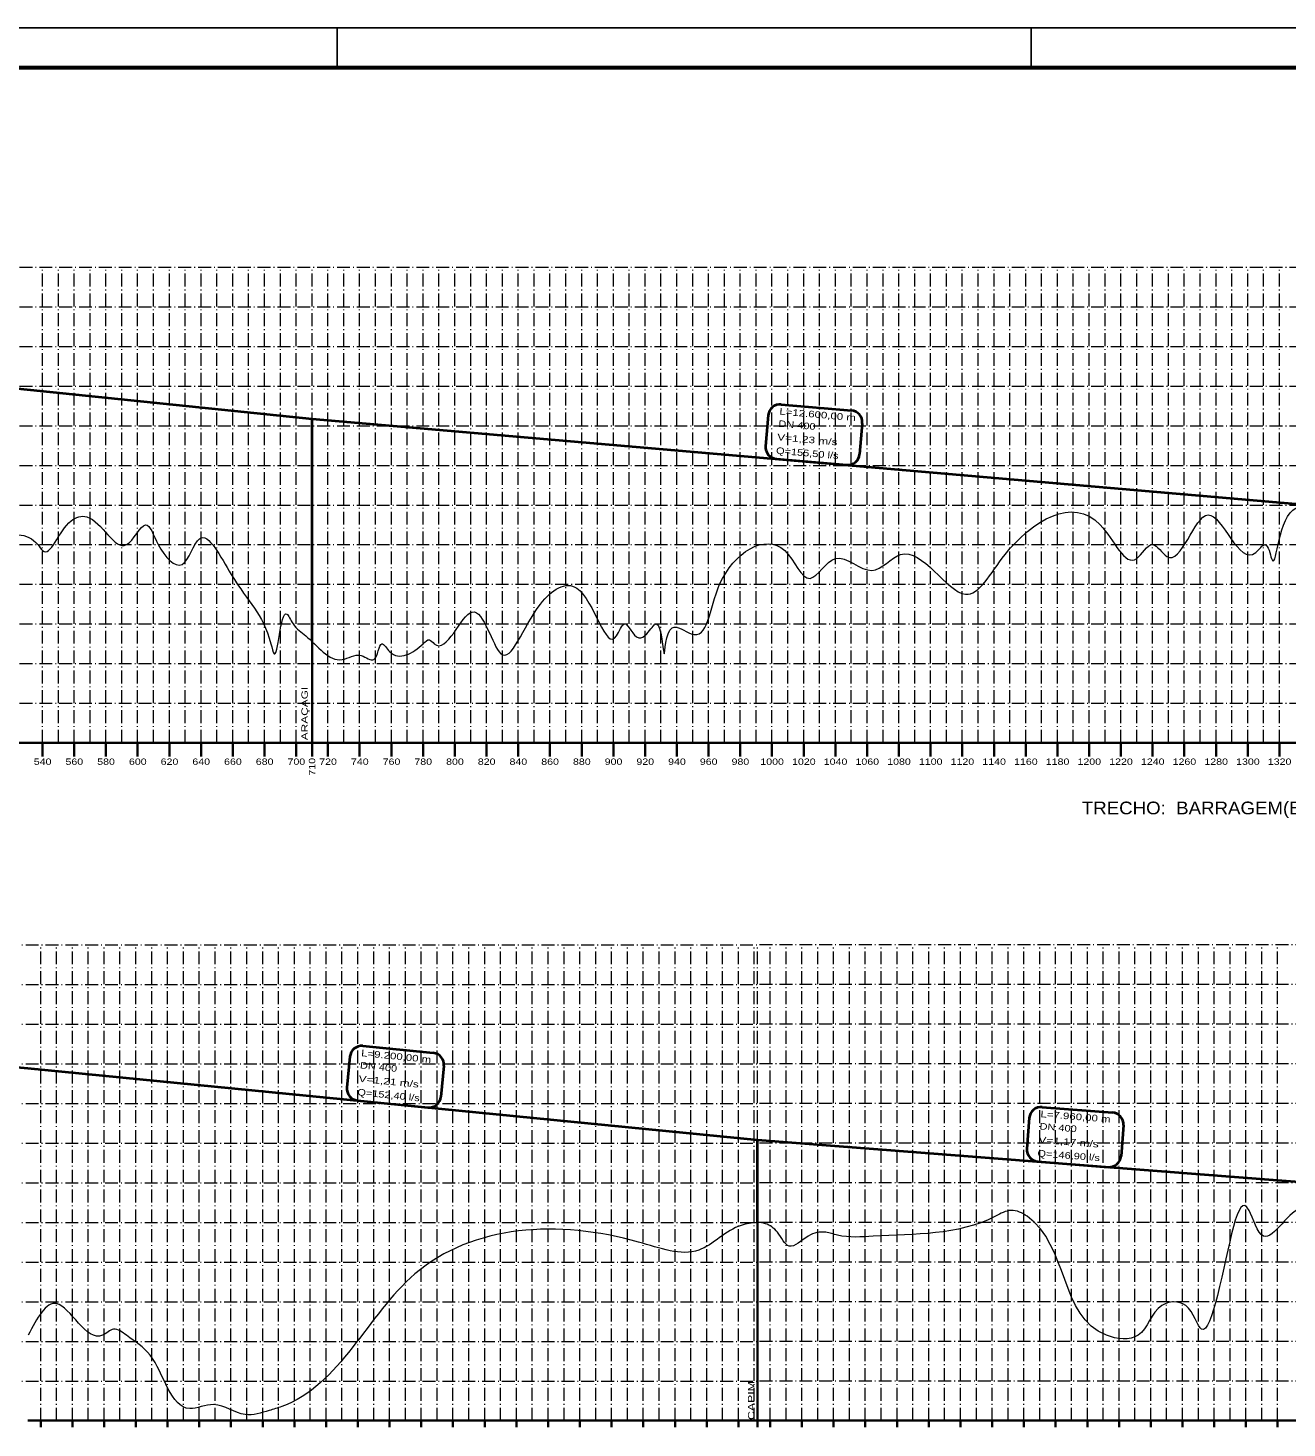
# Model space of a CAD drawing. Extents: x 0 to 1772, y 0 to 1188.
# Drawn here: x 546 to 1181, y 482 to 1188 of the extents above; entities that cross this region are included whole.
import ezdxf
from ezdxf.enums import TextEntityAlignment as Align

# ---------------------------------------------------------------- set-up
doc = ezdxf.new("R2010")
doc.units = 0
doc.header["$LTSCALE"] = 1.3
doc.linetypes.add('DOT_DASHED', pattern=[7.7, 5, -1.2, 0.3, -1.2])
for name, color, linetype, lineweight in [('1', 7, 'DOT_DASHED', 13), ('24', 7, 'Continuous', 35), ('55', 7, 'Continuous', 13), ('56', 7, 'Continuous', 13), ('62', 7, 'Continuous', 13), ('63', 7, 'Continuous', 25), ('9', 7, 'Continuous', 40)]:
    doc.layers.add(name, color=color, linetype=linetype, lineweight=lineweight)

msp = doc.modelspace()

# ---------------------------------------------------------------- linework, layer by layer
at = {"layer": '1'}
for p, q in [((121.175, 1067.213), (1313.175, 1067.213)), ((553.175, 827.213), (553.175, 1067.213)), ((561.175, 827.213), (561.175, 1067.213)), ((569.175, 827.213), (569.175, 1067.213)), ((577.175, 827.213), (577.175, 1067.213)), ((585.175, 827.213), (585.175, 1067.213)), ((593.175, 827.213), (593.175, 1067.213)), ((601.175, 827.213), (601.175, 1067.213)), ((609.175, 827.213), (609.175, 1067.213)), ((617.175, 827.213), (617.175, 1067.213)), ((625.175, 827.213), (625.175, 1067.213)), ((633.175, 827.213), (633.175, 1067.213)), ((641.175, 827.213), (641.175, 1067.213)), ((649.175, 827.213), (649.175, 1067.213)), ((657.175, 827.213), (657.175, 1067.213)), ((665.175, 827.213), (665.175, 1067.213)), ((673.175, 827.213), (673.175, 1067.213)), ((681.175, 827.213), (681.175, 1067.213)), ((689.175, 827.213), (689.175, 1067.213)), ((697.175, 827.213), (697.175, 1067.213)), ((705.175, 827.213), (705.175, 1067.213)), ((713.175, 827.213), (713.175, 1067.213)), ((721.175, 827.213), (721.175, 1067.213)), ((729.175, 827.213), (729.175, 1067.213)), ((737.175, 827.213), (737.175, 1067.213)), ((745.175, 827.213), (745.175, 1067.213)), ((753.175, 827.213), (753.175, 1067.213)), ((761.175, 827.213), (761.175, 1067.213)), ((769.175, 827.213), (769.175, 1067.213)), ((777.175, 827.213), (777.175, 1067.213)), ((785.175, 827.213), (785.175, 1067.213)), ((793.175, 827.213), (793.175, 1067.213)), ((801.175, 827.213), (801.175, 1067.213)), ((809.175, 827.213), (809.175, 1067.213)), ((817.175, 827.213), (817.175, 1067.213)), ((825.175, 827.213), (825.175, 1067.213)), ((833.175, 827.213), (833.175, 1067.213)), ((841.175, 827.213), (841.175, 1067.213)), ((849.175, 827.213), (849.175, 1067.213)), ((857.175, 827.213), (857.175, 1067.213)), ((865.175, 827.213), (865.175, 1067.213)), ((873.175, 827.213), (873.175, 1067.213)), ((881.175, 827.213), (881.175, 1067.213)), ((889.175, 827.213), (889.175, 1067.213)), ((897.175, 827.213), (897.175, 1067.213)), ((905.175, 827.213), (905.175, 1067.213)), ((913.175, 827.213), (913.175, 1067.213)), ((921.175, 827.213), (921.175, 1067.213)), ((929.175, 827.213), (929.175, 1067.213)), ((937.175, 827.213), (937.175, 1067.213)), ((945.175, 827.213), (945.175, 1067.213)), ((953.175, 827.213), (953.175, 1067.213)), ((961.175, 827.213), (961.175, 1067.213)), ((969.175, 827.213), (969.175, 1067.213)), ((977.175, 827.213), (977.175, 1067.213)), ((985.175, 827.213), (985.175, 1067.213)), ((993.175, 827.213), (993.175, 1067.213)), ((1001.175, 827.213), (1001.175, 1067.213)), ((1009.175, 827.213), (1009.175, 1067.213)), ((1017.175, 827.213), (1017.175, 1067.213)), ((1025.175, 827.213), (1025.175, 1067.213)), ((1033.175, 827.213), (1033.175, 1067.213)), ((1041.175, 827.213), (1041.175, 1067.213)), ((1049.175, 827.213), (1049.175, 1067.213)), ((1057.175, 827.213), (1057.175, 1067.213)), ((1065.175, 827.213), (1065.175, 1067.213)), ((1073.175, 827.213), (1073.175, 1067.213)), ((1081.175, 827.213), (1081.175, 1067.213)), ((1089.175, 827.213), (1089.175, 1067.213)), ((1097.175, 827.213), (1097.175, 1067.213)), ((1105.175, 827.213), (1105.175, 1067.213)), ((1113.175, 827.213), (1113.175, 1067.213)), ((1121.175, 827.213), (1121.175, 1067.213)), ((1129.175, 827.213), (1129.175, 1067.213)), ((1137.175, 827.213), (1137.175, 1067.213)), ((1145.175, 827.213), (1145.175, 1067.213)), ((1153.175, 827.213), (1153.175, 1067.213)), ((1153.175, 827.213), (1153.175, 1067.213)), ((1153.175, 827.213), (1153.175, 1067.213)), ((1161.175, 827.213), (1161.175, 1067.213)), ((1169.175, 827.213), (1169.175, 1067.213)), ((1177.175, 827.213), (1177.175, 1067.213)), ((121.175, 1047.213), (1313.175, 1047.213)), ((121.175, 1027.213), (1313.175, 1027.213)), ((121.175, 1007.213), (1313.175, 1007.213)), ((121.175, 987.213), (1313.175, 987.213)), ((121.175, 967.213), (1313.175, 967.213)), ((121.175, 947.213), (1313.175, 947.213)), ((121.175, 927.213), (1313.175, 927.213)), ((121.175, 907.213), (1313.175, 907.213)), ((121.175, 887.213), (1313.175, 887.213)), ((121.175, 867.213), (1313.175, 867.213)), ((121.175, 847.213), (1313.175, 847.213)), ((104.257, 725.251), (913.857, 725.251)), ((552.257, 485.251), (552.257, 725.251)), ((560.257, 485.251), (560.257, 725.251)), ((568.257, 485.251), (568.257, 725.251)), ((576.257, 485.251), (576.257, 725.251)), ((584.257, 485.251), (584.257, 725.251)), ((592.257, 485.251), (592.257, 725.251)), ((600.257, 485.251), (600.257, 725.251)), ((608.257, 485.251), (608.257, 725.251)), ((616.257, 485.251), (616.257, 725.251)), ((624.257, 485.251), (624.257, 725.251)), ((632.257, 485.251), (632.257, 725.251)), ((640.257, 485.251), (640.257, 725.251)), ((648.257, 485.251), (648.257, 725.251)), ((656.257, 485.251), (656.257, 725.251)), ((664.257, 485.251), (664.257, 725.251)), ((672.257, 485.251), (672.257, 725.251)), ((680.257, 485.251), (680.257, 725.251)), ((688.257, 485.251), (688.257, 725.251)), ((696.257, 485.251), (696.257, 725.251)), ((704.257, 485.251), (704.257, 725.251)), ((712.257, 485.251), (712.257, 725.251)), ((720.257, 485.251), (720.257, 725.251)), ((728.257, 485.251), (728.257, 725.251)), ((736.257, 485.251), (736.257, 725.251)), ((744.257, 485.251), (744.257, 725.251)), ((752.257, 485.251), (752.257, 725.251)), ((760.257, 485.251), (760.257, 725.251)), ((768.257, 485.251), (768.257, 725.251)), ((776.257, 485.251), (776.257, 725.251)), ((784.257, 485.251), (784.257, 725.251)), ((792.257, 485.251), (792.257, 725.251)), ((800.257, 485.251), (800.257, 725.251)), ((808.257, 485.251), (808.257, 725.251)), ((816.257, 485.251), (816.257, 725.251)), ((824.257, 485.251), (824.257, 725.251)), ((832.257, 485.251), (832.257, 725.251)), ((840.257, 485.251), (840.257, 725.251)), ((848.257, 485.251), (848.257, 725.251)), ((856.257, 485.251), (856.257, 725.251)), ((864.257, 485.251), (864.257, 725.251)), ((872.257, 485.251), (872.257, 725.251)), ((880.257, 485.251), (880.257, 725.251)), ((888.257, 485.251), (888.257, 725.251)), ((896.257, 485.251), (896.257, 725.251)), ((904.257, 485.251), (904.257, 725.251)), ((912.257, 485.251), (912.257, 725.251)), ((913.857, 485.251), (913.857, 725.251)), ((1321.857, 725.251), (913.857, 725.251)), ((920.257, 485.251), (920.257, 725.251)), ((928.257, 485.251), (928.257, 725.251)), ((936.257, 485.251), (936.257, 725.251)), ((944.257, 485.251), (944.257, 725.251)), ((952.257, 485.251), (952.257, 725.251)), ((960.257, 485.251), (960.257, 725.251)), ((968.257, 485.251), (968.257, 725.251)), ((976.257, 485.251), (976.257, 725.251)), ((984.257, 485.251), (984.257, 725.251)), ((992.257, 485.251), (992.257, 725.251)), ((1000.257, 485.251), (1000.257, 725.251)), ((1008.257, 485.251), (1008.257, 725.251)), ((1016.257, 485.251), (1016.257, 725.251)), ((1024.257, 485.251), (1024.257, 725.251)), ((1032.257, 485.251), (1032.257, 725.251)), ((1040.257, 485.251), (1040.257, 725.251)), ((1048.257, 485.251), (1048.257, 725.251)), ((1056.257, 485.251), (1056.257, 725.251)), ((1064.257, 485.251), (1064.257, 725.251)), ((1072.257, 485.251), (1072.257, 725.251)), ((1080.257, 485.251), (1080.257, 725.251)), ((1088.257, 485.251), (1088.257, 725.251)), ((1096.257, 485.251), (1096.257, 725.251)), ((1104.257, 485.251), (1104.257, 725.251)), ((1112.257, 485.251), (1112.257, 725.251)), ((1120.257, 485.251), (1120.257, 725.251)), ((1128.257, 485.251), (1128.257, 725.251)), ((1136.257, 485.251), (1136.257, 725.251)), ((1144.257, 485.251), (1144.257, 725.251)), ((1152.257, 485.251), (1152.257, 725.251)), ((1160.257, 485.251), (1160.257, 725.251)), ((1168.257, 485.251), (1168.257, 725.251)), ((1176.257, 485.251), (1176.257, 725.251)), ((104.257, 705.251), (913.857, 705.251)), ((1321.857, 705.251), (913.857, 705.251)), ((104.257, 685.251), (913.857, 685.251)), ((1321.857, 685.251), (913.857, 685.251)), ((104.257, 665.251), (913.857, 665.251)), ((1321.857, 665.251), (913.857, 665.251)), ((104.257, 645.251), (913.857, 645.251)), ((1321.857, 645.251), (913.857, 645.251)), ((104.257, 625.251), (913.857, 625.251)), ((1321.857, 625.251), (913.857, 625.251)), ((104.257, 605.251), (913.857, 605.251)), ((1321.857, 605.251), (913.857, 605.251)), ((104.257, 585.251), (913.857, 585.251)), ((1321.857, 585.251), (913.857, 585.251)), ((104.257, 565.251), (913.857, 565.251)), ((1321.857, 565.251), (913.857, 565.251)), ((104.257, 545.251), (913.857, 545.251)), ((1321.857, 545.251), (913.857, 545.251)), ((104.257, 525.251), (913.857, 525.251)), ((1321.857, 525.251), (913.857, 525.251)), ((104.257, 505.251), (913.857, 505.251)), ((1321.857, 505.251), (913.857, 505.251))]:
    msp.add_line(p, q, dxfattribs=at)
at = {"layer": '24'}
msp.add_line((913.857, 485.251), (913.857, 585.251), dxfattribs=at)
at = {"layer": '55'}
msp.add_spline([(121.175, 872.213), (130.775, 867.213), (132.775, 862.213), (134.775, 867.213), (136.375, 877.213), (137.975, 867.213), (139.575, 877.213), (149.175, 900.213), (153.175, 887.213), (155.575, 872.213), (165.975, 905.213), (181.975, 897.213), (202.775, 856.213), (243.575, 896.213), (251.575, 887.213), (258.775, 897.213), (274.775, 901.213), (282.775, 905.213), (304.375, 905.213), (317.175, 897.213), (325.175, 877.213), (326.775, 882.213), (328.375, 877.213), (345.175, 862.213), (359.575, 887.213), (384.375, 909.213), (405.175, 907.213), (418.775, 910.213), (450.775, 914.213), (458.775, 908.213), (491.575, 937.213), (505.175, 922.213), (509.175, 920.213), (541.175, 932.213), (550.775, 927.213), (553.175, 924.213), (567.575, 939.213), (575.575, 941.213), (595.575, 927.213), (605.175, 937.213), (611.575, 927.213), (623.575, 917.213), (632.375, 930.213), (648.375, 912.213), (668.375, 877.213), (669.975, 872.213), (676.375, 892.213), (679.575, 887.213), (685.975, 881.213), (704.375, 869.213), (713.975, 871.213), (720.375, 869.213), (724.375, 877.213), (728.375, 873.213), (745.175, 877.213), (748.375, 879.213), (750.775, 877.213), (769.975, 893.213), (784.375, 872.213), (804.375, 897.213), (822.775, 905.213), (842.775, 881.213), (846.775, 887.213), (853.975, 880.213), (857.975, 882.213), (862.775, 887.213), (866.775, 872.213), (870.775, 885.213), (880.375, 882.213), (894.775, 907.213), (927.575, 924.213), (940.375, 910.213), (953.175, 920.213), (971.575, 914.213), (985.975, 922.213), (1018.775, 902.213), (1038.775, 922.213), (1086.775, 937.213), (1105.175, 920.213), (1113.175, 927.213), (1120.375, 921.213), (1141.175, 942.213), (1165.175, 923.213), (1169.975, 927.213), (1173.175, 920.213), (1183.928, 944.69), (1188.375, 946.213), (1193.175, 942.213)], degree=3, dxfattribs=at)
at = {"layer": '56'}
for points in [[(1321.875, 538.34), (1301.875, 518.34), (1286.675, 528.34), (1274.675, 508.34), (1261.875, 528.34), (1232.275, 596.34), (1224.275, 578.34), (1216.275, 595.34), (1208.275, 568.34), (1189.075, 592.34), (1169.075, 578.34), (1161.875, 591.34), (1145.875, 548.34), (1137.875, 531.34), (1129.875, 543.34), (1117.875, 543.34), (1105.875, 528.34), (1089.875, 528.34), (1049.875, 588.34), (1041.875, 591.34), (1033.875, 588.34), (972.275, 578.34), (954.275, 578.84), (948.275, 580.34), (939.475, 578.34), (929.875, 573.34), (923.875, 580.328), (917.898, 584.62), (913.857, 585.251)], [(913.857, 585.251), (905.576, 583.798), (884.275, 571.34), (853.875, 575.34), (741.075, 559.34), (673.875, 492.34), (667.475, 490.34), (655.475, 488.34), (639.475, 493.34), (627.475, 491.34), (607.475, 518.34), (595.475, 528.34), (589.075, 531.34), (583.475, 528.34), (560.275, 544.34), (545.875, 528.34)]]:
    msp.add_spline(points, degree=3, dxfattribs=at)
at = {"layer": '62', "lineweight": 35}
for p, q in [((689.175, 827.213), (689.175, 879.126)), ((553.175, 827.213), (553.175, 820.386)), ((569.175, 827.213), (569.175, 820.386)), ((585.175, 827.213), (585.175, 820.386)), ((601.175, 827.213), (601.175, 820.386)), ((617.175, 827.213), (617.175, 820.386)), ((633.175, 827.213), (633.175, 820.386)), ((649.175, 827.213), (649.175, 820.386)), ((665.175, 827.213), (665.175, 820.386)), ((681.175, 827.213), (681.175, 820.386)), ((689.175, 827.213), (689.175, 820.386)), ((697.175, 827.213), (697.175, 820.386)), ((713.175, 827.213), (713.175, 820.386)), ((729.175, 827.213), (729.175, 820.386)), ((745.175, 827.213), (745.175, 820.386)), ((761.175, 827.213), (761.175, 820.386)), ((777.175, 827.213), (777.175, 820.386)), ((793.175, 827.213), (793.175, 820.386)), ((809.175, 827.213), (809.175, 820.386)), ((825.175, 827.213), (825.175, 820.386)), ((841.175, 827.213), (841.175, 820.386)), ((857.175, 827.213), (857.175, 820.386)), ((873.175, 827.213), (873.175, 820.386)), ((889.175, 827.213), (889.175, 820.386)), ((905.175, 827.213), (905.175, 820.386)), ((921.175, 827.213), (921.175, 820.386)), ((937.175, 827.213), (937.175, 820.386)), ((953.175, 827.213), (953.175, 820.386)), ((969.175, 827.213), (969.175, 820.386)), ((985.175, 827.213), (985.175, 820.386)), ((1001.175, 827.213), (1001.175, 820.386)), ((1017.175, 827.213), (1017.175, 820.386)), ((1033.175, 827.213), (1033.175, 820.386)), ((1049.175, 827.213), (1049.175, 820.386)), ((1065.175, 827.213), (1065.175, 820.386)), ((1081.175, 827.213), (1081.175, 820.386)), ((1097.175, 827.213), (1097.175, 820.386)), ((1113.175, 827.213), (1113.175, 820.386)), ((1129.175, 827.213), (1129.175, 820.386)), ((1145.175, 827.213), (1145.175, 820.386)), ((1161.175, 827.213), (1161.175, 820.386)), ((1177.175, 827.213), (1177.175, 820.386)), ((913.857, 485.251), (545.857, 485.251)), ((552.257, 485.251), (552.257, 481.901)), ((568.257, 485.251), (568.257, 481.901)), ((584.257, 485.251), (584.257, 481.901)), ((600.257, 485.251), (600.257, 481.901)), ((616.257, 485.251), (616.257, 481.901)), ((632.257, 485.251), (632.257, 481.901)), ((648.257, 485.251), (648.257, 481.901)), ((664.257, 485.251), (664.257, 481.901)), ((680.257, 485.251), (680.257, 481.901)), ((696.257, 485.251), (696.257, 481.901)), ((712.257, 485.251), (712.257, 481.901)), ((728.257, 485.251), (728.257, 481.901)), ((744.257, 485.251), (744.257, 481.901)), ((760.257, 485.251), (760.257, 481.901)), ((776.257, 485.251), (776.257, 481.901)), ((792.257, 485.251), (792.257, 481.901)), ((808.257, 485.251), (808.257, 481.901)), ((824.257, 485.251), (824.257, 481.901)), ((840.257, 485.251), (840.257, 481.901)), ((856.257, 485.251), (856.257, 481.901)), ((872.257, 485.251), (872.257, 481.901)), ((888.257, 485.251), (888.257, 481.901)), ((904.257, 485.251), (904.257, 481.901)), ((913.857, 485.251), (913.857, 481.901)), ((1321.857, 485.251), (913.857, 485.251)), ((920.257, 485.251), (920.257, 481.901)), ((936.257, 485.251), (936.257, 481.901)), ((952.257, 485.251), (952.257, 481.901)), ((968.257, 485.251), (968.257, 481.901)), ((984.257, 485.251), (984.257, 481.901)), ((1000.257, 485.251), (1000.257, 481.901)), ((1016.257, 485.251), (1016.257, 481.901)), ((1032.257, 485.251), (1032.257, 481.901)), ((1048.257, 485.251), (1048.257, 481.901)), ((1064.257, 485.251), (1064.257, 481.901)), ((1080.257, 485.251), (1080.257, 481.901)), ((1096.257, 485.251), (1096.257, 481.901)), ((1112.257, 485.251), (1112.257, 481.901)), ((1128.257, 485.251), (1128.257, 481.901)), ((1144.257, 485.251), (1144.257, 481.901)), ((1160.257, 485.251), (1160.257, 481.901)), ((1176.257, 485.251), (1176.257, 481.901))]:
    msp.add_line(p, q, dxfattribs=at)
msp.add_lwpolyline([(121.175, 827.213), (401.175, 827.213), (1193.175, 827.213)], dxfattribs=at)
at = {"layer": '63'}
for p, q in [((-0.167, 1187.873), (1771.833, 1187.873)), ((701.833, 1167.873), (701.833, 1187.873)), ((1051.833, 1167.873), (1051.833, 1187.873))]:
    msp.add_line(p, q, dxfattribs=at)
at = {"layer": '63', "lineweight": 60}
msp.add_lwpolyline([(49.833, 1167.873), (1751.833, 1167.873), (1751.833, 19.873), (49.833, 19.873)], close=True, dxfattribs=at)
at = {"layer": '9'}
for p, q in [((165.176, 1044.943), (689.174, 990.643)), ((925.772, 997.968), (961.275, 994.909)), ((689.175, 990.643), (1193.131, 947.217)), ((689.175, 879.126), (689.175, 990.643)), ((919.279, 992.506), (917.939, 976.953)), ((966.737, 988.416), (965.397, 972.863)), ((923.402, 970.46), (958.904, 967.4)), ((714.832, 674.277), (750.295, 670.785)), ((708.273, 668.894), (706.743, 653.359)), ((755.678, 664.226), (754.148, 648.69)), ((712.126, 646.8), (747.589, 643.307)), ((1057.427, 643.497), (1092.955, 640.743)), ((1050.982, 637.979), (1049.775, 622.415)), ((1098.473, 634.297), (1097.267, 618.734)), ((913.857, 626.933), (1232.257, 602.251)), ((913.857, 585.251), (913.857, 626.933)), ((1055.294, 615.969), (1090.821, 613.215))]:
    msp.add_line(p, q, dxfattribs=at)
msp.add_lwpolyline([(104.257, 702.369), (545.857, 663.174), (913.857, 626.933)], dxfattribs=at)
for centre, radius, start, end in [((925.257, 991.99), 6, 85.07495, 175.07495), ((689.178, 990.683), 0.04, 264.08379, 265.07495), ((960.76, 988.931), 6, 355.07495, 85.07495), ((923.917, 976.438), 6, 175.07495, 265.07495), ((959.419, 973.378), 6, 265.07495, 355.07495), ((714.244, 668.306), 6, 84.37566, 174.37566), ((749.707, 664.814), 6, 354.37566, 84.37566), ((712.714, 652.771), 6, 174.37566, 264.37566), ((748.177, 649.279), 6, 264.37566, 354.37566), ((1056.964, 637.515), 6, 85.56737, 175.56737), ((1092.491, 634.761), 6, 355.56737, 85.56737), ((1055.757, 621.951), 6, 175.56737, 265.56737), ((1091.285, 619.197), 6, 265.56737, 355.56737)]:
    msp.add_arc(centre, radius, start, end, dxfattribs=at)

# ---------------------------------------------------------------- texts
at = {"layer": '24'}
for s, width, p in [('ARAÇAGI', 1.4, (687.014, 828.53)), ('CAPIM', 1.45, (912.301, 485.58))]:
    msp.add_text(s, height=3.2, rotation=90, dxfattribs=dict(at, width=width)).set_placement(p)
for s, height, width, p in [('540', 3.2, 1.25, (553.24, 816.125)), ('560', 3.2, 1.25, (569.24, 816.125)), ('580', 3.2, 1.25, (585.24, 816.125)), ('600', 3.2, 1.25, (601.24, 816.125)), ('620', 3.2, 1.25, (617.24, 816.125)), ('640', 3.2, 1.25, (633.24, 816.125)), ('660', 3.2, 1.25, (649.24, 816.125)), ('680', 3.2, 1.25, (665.24, 816.125)), ('700', 3.2, 1.25, (681.24, 816.125)), ('720', 3.2, 1.25, (697.24, 816.125)), ('740', 3.2, 1.25, (713.24, 816.125)), ('760', 3.2, 1.25, (729.24, 816.125)), ('780', 3.2, 1.25, (745.24, 816.125)), ('800', 3.2, 1.25, (761.24, 816.125)), ('820', 3.2, 1.25, (777.24, 816.125)), ('840', 3.2, 1.25, (793.24, 816.125)), ('860', 3.2, 1.25, (809.24, 816.125)), ('880', 3.2, 1.25, (825.24, 816.125)), ('900', 3.2, 1.25, (841.24, 816.125)), ('920', 3.2, 1.25, (857.24, 816.125)), ('940', 3.2, 1.25, (873.24, 816.125)), ('960', 3.2, 1.25, (889.24, 816.125)), ('980', 3.2, 1.25, (905.24, 816.125)), ('1000', 3.2, 1.25, (921.24, 816.125)), ('1020', 3.2, 1.25, (937.24, 816.125)), ('1040', 3.2, 1.25, (953.24, 816.125)), ('1060', 3.2, 1.25, (969.24, 816.125)), ('1080', 3.2, 1.25, (985.24, 816.125)), ('1100', 3.2, 1.25, (1001.24, 816.125)), ('1120', 3.2, 1.25, (1017.24, 816.125)), ('1140', 3.2, 1.25, (1033.24, 816.125)), ('1160', 3.2, 1.25, (1049.24, 816.125)), ('1180', 3.2, 1.25, (1065.24, 816.125)), ('1200', 3.2, 1.25, (1081.24, 816.125)), ('1220', 3.2, 1.25, (1097.24, 816.125)), ('1240', 3.2, 1.25, (1113.24, 816.125)), ('1260', 3.2, 1.25, (1129.24, 816.125)), ('1280', 3.2, 1.25, (1145.24, 816.125)), ('1300', 3.2, 1.25, (1161.24, 816.125)), ('1320', 3.2, 1.25, (1177.24, 816.125)), ('TRECHO:  BARRAGEM(EB1/1)   A  PILÕEZINHOS', 6.4, 1.1, (1185.492, 791.171))]:
    msp.add_text(s, height=height, dxfattribs=dict(at, width=width)).set_placement(p, align=Align.CENTER)
at = {"layer": '24', "width": 1.25}
msp.add_text('710', height=3.2, rotation=90, dxfattribs=at).set_placement((690.746, 815.151), align=Align.CENTER)
at = {"layer": '9'}
for s, rotation, width, p in [('L=12.600,00 m', 355.075, 1.3, (924.814, 992.853)), ('DN 400', 355.075, 1.25, (924.284, 986.696)), ('V=1,23 m/s', 355.075, 1.35, (923.698, 979.898)), ('Q=155,50 l/s', 355.075, 1.25, (923.112, 973.099)), ('L=9.200,00 m', 354.376, 1.3, (713.812, 669.174)), ('DN 400', 354.376, 1.25, (713.206, 663.024)), ('V=1,21 m/s', 354.376, 1.35, (712.537, 656.233)), ('Q=152,40 l/s', 354.376, 1.25, (711.869, 649.443)), ('L=7.960,00 m', 355.567, 1.3, (1056.514, 638.374)), ('V=1,17 m/s', 355.567, 1.35, (1055.509, 625.409)), ('DN 400', 355.567, 1.25, (1056.036, 632.213)), ('Q=146,90 l/s', 355.567, 1.25, (1054.981, 618.606))]:
    msp.add_text(s, height=3.319, rotation=rotation, dxfattribs=dict(at, width=width)).set_placement(p)

doc.saveas('drawing.dxf')
